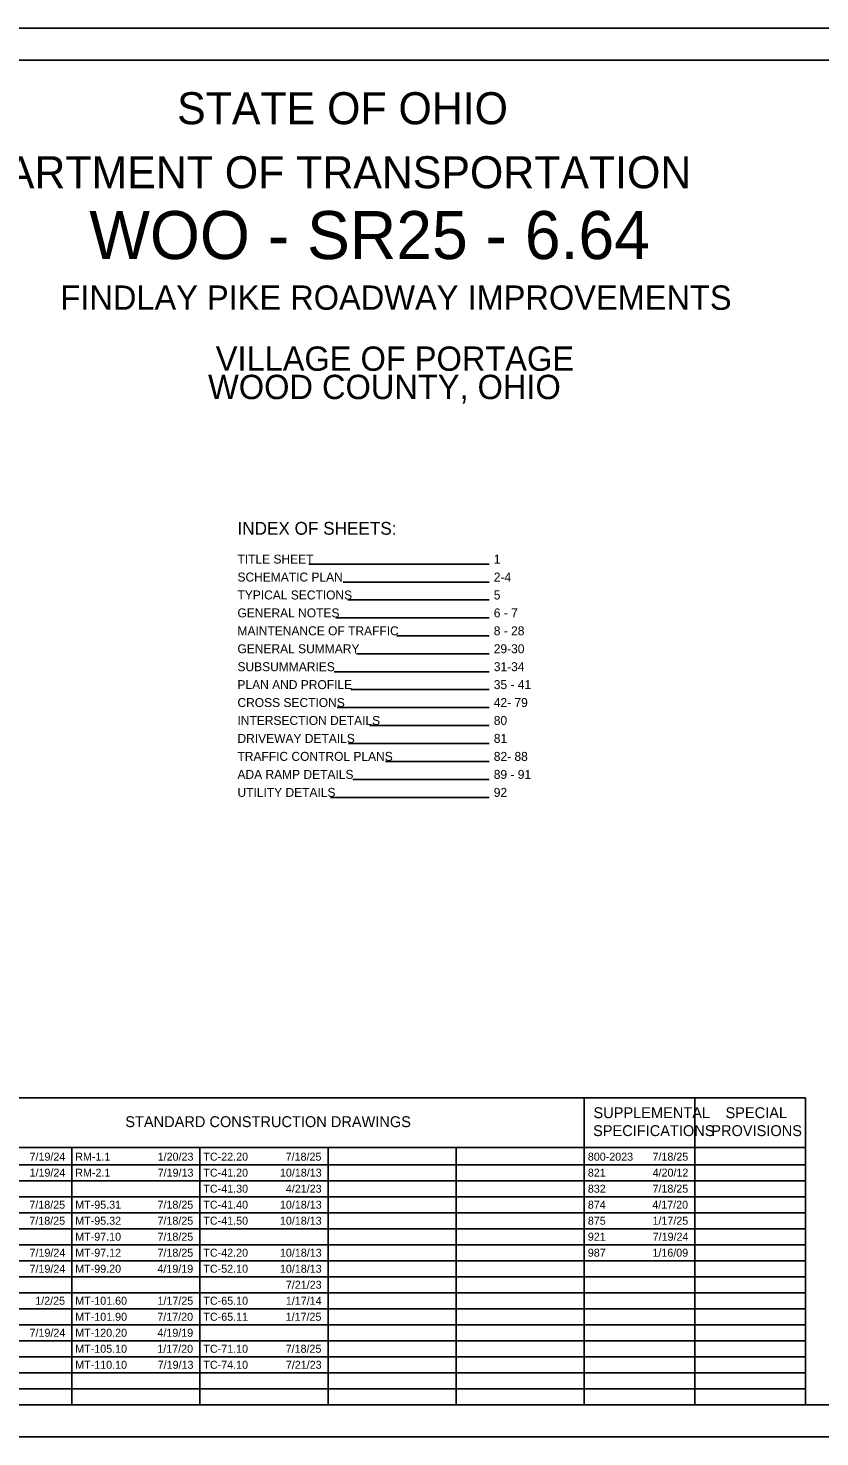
# Model space of a CAD drawing. Extents: x -107 to 120, y -81 to 213.
# Drawn here: x 15.36 to 27.71, y 1.57 to 23.57 of the extents above; entities that cross this region are included whole.
import ezdxf

# ---------------------------------------------------------------- set-up
doc = ezdxf.new("R2010")
doc.units = 0
for name, color, linetype in [('SH_Border', 7, 'Continuous'), ('SH_Cut_Line', 7, 'Continuous'), ('SH_Data', 7, 'Continuous'), ('SH_Text', 7, 'Continuous')]:
    doc.layers.add(name, color=color, linetype=linetype)

msp = doc.modelspace()

# ---------------------------------------------------------------- linework, layer by layer
at = {"layer": 'SH_Border'}
msp.add_lwpolyline([(5.389, 23.068), (37.389, 23.068), (37.389, 2.068), (5.389, 2.068)], close=True, dxfattribs=at)
at = {"layer": 'SH_Cut_Line'}
msp.add_lwpolyline([(3.889, 1.568), (37.889, 1.568), (37.889, 23.568), (3.889, 23.568)], close=True, dxfattribs=at)
at = {"layer": 'SH_Data'}
for p, q in [((14.039, 6.86), (27.489, 6.86)), ((24.039, 2.068), (24.039, 6.86)), ((25.764, 2.068), (25.764, 6.86)), ((27.489, 2.068), (27.489, 6.86)), ((14.039, 6.089), (27.489, 6.089)), ((16.039, 2.068), (16.039, 6.089)), ((18.039, 2.068), (18.039, 6.089)), ((20.039, 2.068), (20.039, 6.089)), ((22.039, 2.068), (22.039, 6.089)), ((14.039, 5.818), (27.489, 5.818)), ((14.039, 5.568), (27.489, 5.568)), ((14.039, 5.568), (27.489, 5.568)), ((14.039, 5.318), (27.489, 5.318)), ((14.039, 5.068), (27.489, 5.068)), ((14.039, 4.818), (27.489, 4.818)), ((14.039, 4.568), (27.489, 4.568)), ((14.039, 4.318), (27.489, 4.318)), ((14.039, 4.068), (27.489, 4.068)), ((14.039, 3.818), (27.489, 3.818)), ((14.039, 3.568), (27.489, 3.568)), ((14.039, 3.318), (27.489, 3.318)), ((14.039, 3.068), (27.489, 3.068)), ((14.039, 2.818), (27.489, 2.818)), ((14.039, 2.568), (27.489, 2.568)), ((14.039, 2.318), (27.489, 2.318))]:
    msp.add_line(p, q, dxfattribs=at)
at = {"layer": 'SH_Text'}
for p, q in [((19.74, 15.198), (22.553, 15.198)), ((20.276, 14.918), (22.553, 14.918)), ((20.346, 14.638), (22.553, 14.638)), ((20.159, 14.358), (22.553, 14.358)), ((21.115, 14.078), (22.553, 14.078)), ((20.484, 13.798), (22.553, 13.798)), ((20.136, 13.518), (22.553, 13.518)), ((20.396, 13.238), (22.553, 13.238)), ((20.18, 12.958), (22.553, 12.958)), ((20.692, 12.678), (22.553, 12.678)), ((20.357, 12.398), (22.553, 12.398)), ((20.936, 12.117), (22.553, 12.117)), ((20.424, 11.836), (22.553, 11.836)), ((20.079, 11.555), (22.553, 11.555))]:
    msp.add_line(p, q, dxfattribs=at)

# ---------------------------------------------------------------- texts
for s, height, p in [('STATE OF OHIO', 0.5, (17.684, 22.068)), ('DEPARTMENT OF TRANSPORTATION', 0.5, (13.636, 21.068)), ('WOO - SR25 - 6.64', 0.75, (16.313, 19.962)), ('FINDLAY PIKE ROADWAY IMPROVEMENTS', 0.38, (15.863, 19.17)), ('VILLAGE OF PORTAGE', 0.38, (18.287, 18.217)), ('WOOD COUNTY, OHIO', 0.38, (18.167, 17.775)), ('INDEX OF SHEETS:', 0.2, (18.626, 15.657)), ('TITLE SHEET', 0.14, (18.626, 15.206)), ('1', 0.14, (22.626, 15.206)), ('SCHEMATIC PLAN', 0.14, (18.626, 14.926)), ('2-4', 0.14, (22.626, 14.926)), ('TYPICAL SECTIONS', 0.14, (18.626, 14.646)), ('5', 0.14, (22.626, 14.646)), ('GENERAL NOTES', 0.14, (18.626, 14.366)), ('6 - 7', 0.14, (22.626, 14.366)), ('MAINTENANCE OF TRAFFIC', 0.14, (18.626, 14.086)), ('8 - 28', 0.14, (22.626, 14.086)), ('GENERAL SUMMARY', 0.14, (18.626, 13.806)), ('29-30', 0.14, (22.626, 13.806)), ('SUBSUMMARIES', 0.14, (18.626, 13.526)), ('31-34', 0.14, (22.626, 13.526)), ('PLAN AND PROFILE', 0.14, (18.626, 13.246)), ('35 - 41', 0.14, (22.626, 13.246)), ('CROSS SECTIONS', 0.14, (18.626, 12.966)), ('42- 79', 0.14, (22.626, 12.966)), ('INTERSECTION DETAILS', 0.14, (18.626, 12.686)), ('80', 0.14, (22.626, 12.686)), ('DRIVEWAY DETAILS', 0.14, (18.626, 12.406)), ('81', 0.14, (22.626, 12.406)), ('TRAFFIC CONTROL PLANS', 0.14, (18.626, 12.125)), ('82- 88', 0.14, (22.626, 12.125)), ('ADA RAMP DETAILS', 0.14, (18.626, 11.844)), ('89 - 91', 0.14, (22.626, 11.844)), ('UTILITY DETAILS', 0.14, (18.626, 11.563)), ('92', 0.14, (22.626, 11.563)), ('SUPPLEMENTAL', 0.17, (24.182, 6.545)), ('SPECIAL', 0.17, (26.243, 6.545)), ('STANDARD CONSTRUCTION DRAWINGS', 0.17, (16.875, 6.405)), ('SPECIFICATIONS', 0.17, (24.176, 6.265)), ('PROVISIONS', 0.17, (26.021, 6.265)), ('7/19/24', 0.125, (15.381, 5.881)), ('RM-1.1', 0.125, (16.094, 5.881)), ('1/20/23', 0.125, (17.381, 5.881)), ('TC-22.20', 0.125, (18.094, 5.881)), ('7/18/25', 0.125, (19.378, 5.881)), ('800-2023', 0.125, (24.094, 5.881)), ('7/18/25', 0.125, (25.103, 5.881)), ('1/19/24', 0.125, (15.381, 5.631)), ('RM-2.1', 0.125, (16.094, 5.631)), ('7/19/13', 0.125, (17.381, 5.631)), ('TC-41.20', 0.125, (18.094, 5.631)), ('10/18/13', 0.125, (19.289, 5.631)), ('821', 0.125, (24.094, 5.631)), ('4/20/12', 0.125, (25.105, 5.631)), ('TC-41.30', 0.125, (18.094, 5.381)), ('4/21/23', 0.125, (19.381, 5.381)), ('832', 0.125, (24.094, 5.381)), ('7/18/25', 0.125, (25.103, 5.381)), ('7/18/25', 0.125, (15.378, 5.131)), ('MT-95.31', 0.125, (16.094, 5.131)), ('7/18/25', 0.125, (17.378, 5.131)), ('TC-41.40', 0.125, (18.094, 5.131)), ('10/18/13', 0.125, (19.289, 5.131)), ('874', 0.125, (24.094, 5.131)), ('4/17/20', 0.125, (25.1, 5.131)), ('7/18/25', 0.125, (15.378, 4.881)), ('MT-95.32', 0.125, (16.094, 4.881)), ('7/18/25', 0.125, (17.378, 4.881)), ('TC-41.50', 0.125, (18.094, 4.881)), ('10/18/13', 0.125, (19.289, 4.881)), ('875', 0.125, (24.094, 4.881)), ('1/17/25', 0.125, (25.103, 4.881)), ('MT-97.10', 0.125, (16.094, 4.631)), ('7/18/25', 0.125, (17.378, 4.631)), ('921', 0.125, (24.094, 4.631)), ('7/19/24', 0.125, (25.106, 4.631)), ('7/19/24', 0.125, (15.381, 4.381)), ('MT-97.12', 0.125, (16.094, 4.381)), ('7/18/25', 0.125, (17.378, 4.381)), ('TC-42.20', 0.125, (18.094, 4.381)), ('10/18/13', 0.125, (19.289, 4.381)), ('987', 0.125, (24.094, 4.381)), ('1/16/09', 0.125, (25.102, 4.381)), ('7/19/24', 0.125, (15.381, 4.131)), ('MT-99.20', 0.125, (16.094, 4.131)), ('4/19/19', 0.125, (17.377, 4.131)), ('TC-52.10', 0.125, (18.094, 4.131)), ('10/18/13', 0.125, (19.289, 4.131)), ('7/21/23', 0.125, (19.381, 3.881)), ('1/2/25', 0.125, (15.47, 3.631)), ('MT-101.60', 0.125, (16.094, 3.631)), ('1/17/25', 0.125, (17.378, 3.631)), ('TC-65.10', 0.125, (18.094, 3.631)), ('1/17/14', 0.125, (19.381, 3.631)), ('MT-101.90', 0.125, (16.094, 3.381)), ('7/17/20', 0.125, (17.375, 3.381)), ('TC-65.11', 0.125, (18.094, 3.381)), ('1/17/25', 0.125, (19.378, 3.381)), ('7/19/24', 0.125, (15.381, 3.131)), ('MT-120.20', 0.125, (16.094, 3.131)), ('4/19/19', 0.125, (17.377, 3.131)), ('MT-105.10', 0.125, (16.094, 2.881)), ('1/17/20', 0.125, (17.375, 2.881)), ('TC-71.10', 0.125, (18.094, 2.881)), ('7/18/25', 0.125, (19.378, 2.881)), ('MT-110.10', 0.125, (16.094, 2.631)), ('7/19/13', 0.125, (17.381, 2.631)), ('TC-74.10', 0.125, (18.094, 2.631)), ('7/21/23', 0.125, (19.381, 2.631))]:
    msp.add_text(s, height=height, dxfattribs=at).set_placement(p)

doc.saveas('drawing.dxf')
